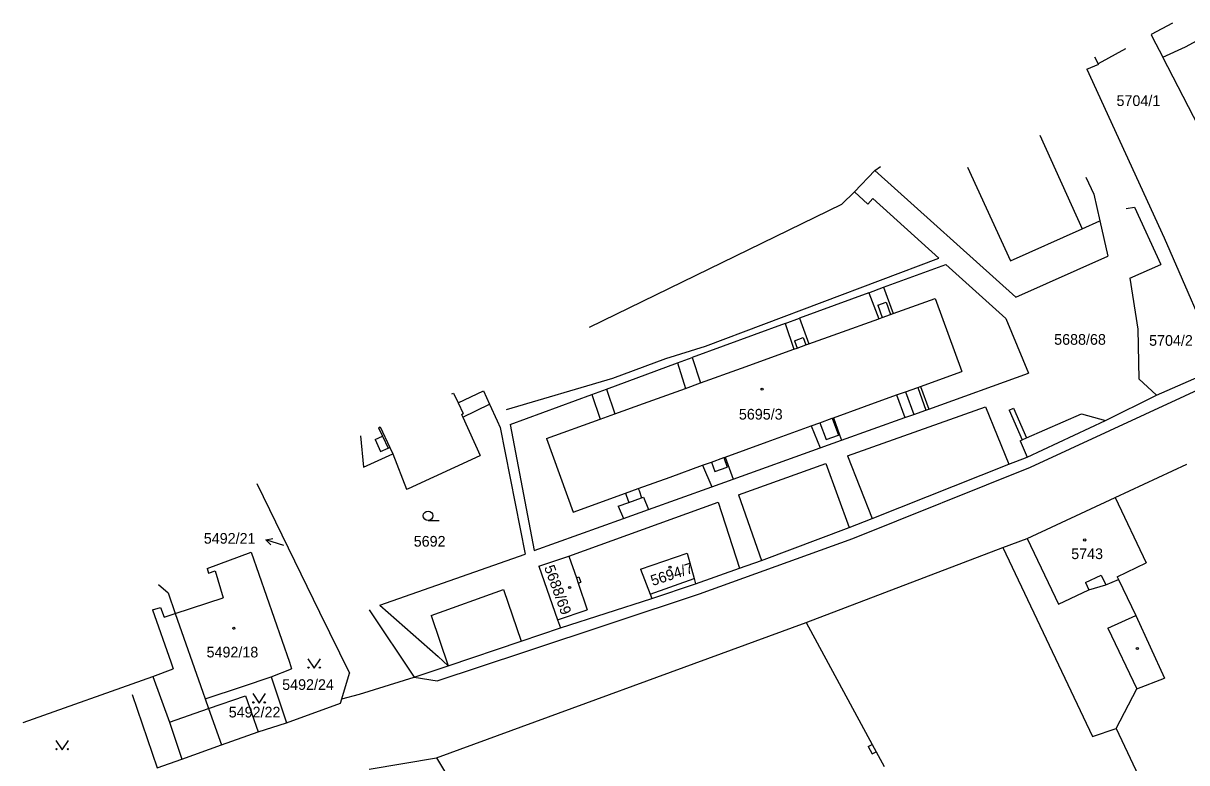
# Model space of a CAD drawing. Extents: x -717507 to -715515, y -957700 to -954941.
# Drawn here: x -716308.1 to -716123.2, y -955290.3 to -955172.6 of the extents above; entities that cross this region are included whole.
import ezdxf

# ---------------------------------------------------------------- set-up
doc = ezdxf.new("R2010")
doc.units = 0
for name, color, linetype in [('Hranice parcel', 7, 'Continuous'), ('Parcelní čísla', 7, 'Continuous'), ('Pop  PČ popisy', 7, 'Continuous'), ('Vnitřní kresba', 7, 'Continuous'), ('Značky budov', 7, 'Continuous'), ('Značky kultur', 7, 'Continuous')]:
    doc.layers.add(name, color=color, linetype=linetype)

msp = doc.modelspace()

# ---------------------------------------------------------------- linework, layer by layer
at = {"layer": 'Hranice parcel'}
for points in [[(-716125.44, -955172.61), (-716128.81, -955174.42)], [(-716126.97, -955178), (-716123.36, -955176.36), (-716118.59, -955173.74)], [(-716128.81, -955174.42), (-716128.64, -955174.77)], [(-716128.64, -955174.77), (-716126.97, -955178)], [(-716137.2, -955179.03), (-716132.84, -955176.61)], [(-716139.07, -955179.92), (-716137.16, -955179.1)], [(-716137.81, -955177.98), (-716137.25, -955179.06)], [(-716137.25, -955179.06), (-716137.2, -955179.03)], [(-716137.16, -955179.1), (-716137.2, -955179.03)], [(-716115.27, -955200.63), (-716115.56, -955200.09), (-716126.97, -955178)], [(-716139.07, -955179.92), (-716126.78, -955206.75)], [(-716175.98, -955199.46), (-716172.74, -955196.06)], [(-716172.74, -955196.06), (-716171.87, -955195.41)], [(-716172.74, -955196.06), (-716150.33, -955216.18)], [(-716158.01, -955195.5), (-716151.21, -955210.39)], [(-716139.23, -955197.08), (-716137.92, -955199.78)], [(-716177.97, -955201.41), (-716175.98, -955199.46)], [(-716175.98, -955199.46), (-716173.88, -955201.39)], [(-716137.92, -955199.78), (-716136.96, -955204.06)], [(-716218.13, -955220.98), (-716177.97, -955201.41)], [(-716173.88, -955201.39), (-716173.08, -955200.5)], [(-716173.08, -955200.5), (-716162.57, -955209.98)], [(-716132.8, -955202.11), (-716131.48, -955201.9)], [(-716131.48, -955201.9), (-716127.26, -955210.98)], [(-716151.21, -955210.39), (-716139.77, -955205.31)], [(-716139.77, -955205.31), (-716136.96, -955204.06)], [(-716136.96, -955204.06), (-716135.69, -955209.66)], [(-716126.78, -955206.75), (-716117.79, -955227.32)], [(-716199.69, -955223.98), (-716162.57, -955209.98)], [(-716171.36, -955214.62), (-716161.46, -955210.98)], [(-716161.46, -955210.98), (-716151.94, -955219.57)], [(-716150.33, -955216.18), (-716135.69, -955209.66)], [(-716132.22, -955213.17), (-716127.26, -955210.98)], [(-716173.71, -955215.48), (-716171.36, -955214.62)], [(-716132.22, -955213.17), (-716130.95, -955221.31)], [(-716173.71, -955215.48), (-716184.73, -955219.54)], [(-716187.03, -955220.38), (-716184.73, -955219.54)], [(-716151.94, -955219.57), (-716148.33, -955228.31)], [(-716187.03, -955220.38), (-716201.77, -955225.8)], [(-716130.95, -955221.31), (-716130.78, -955229.17)], [(-716205.97, -955225.96), (-716199.69, -955223.98)], [(-716204.11, -955226.66), (-716201.77, -955225.8)], [(-716215.4, -955230.81), (-716204.11, -955226.66)], [(-716214.42, -955229.06), (-716205.97, -955225.96)], [(-716127.97, -955231.77), (-716117.79, -955227.32)], [(-716231.28, -955234.08), (-716214.42, -955229.06)], [(-716164.18, -955234), (-716148.33, -955228.31)], [(-716130.78, -955229.17), (-716127.97, -955231.77)], [(-716234.96, -955231.09), (-716234, -955233.23)], [(-716217.72, -955231.66), (-716215.4, -955230.81)], [(-716238.27, -955235.3), (-716234, -955233.23)], [(-716234, -955233.23), (-716232.79, -955235.85)], [(-716230.72, -955236.44), (-716217.72, -955231.66)], [(-716136.09, -955235.84), (-716127.97, -955231.77)], [(-716167.97, -955235.36), (-716166.55, -955234.88)], [(-716166.55, -955234.88), (-716164.62, -955234.17)], [(-716164.62, -955234.17), (-716164.18, -955234)], [(-716238.27, -955235.3), (-716235.47, -955241.41)], [(-716232.79, -955235.85), (-716232.33, -955236.92)], [(-716232.33, -955236.92), (-716228.33, -955257.07)], [(-716230.72, -955236.44), (-716226.89, -955256.5)], [(-716178.05, -955238.97), (-716167.97, -955235.36)], [(-716148.55, -955241.63), (-716136.09, -955235.84)], [(-716254.5, -955238.25), (-716254.03, -955243.26)], [(-716195.28, -955245.16), (-716181.44, -955240.19)], [(-716181.44, -955240.19), (-716178.05, -955238.97)], [(-716254.03, -955243.26), (-716249.39, -955241.11)], [(-716249.39, -955241.11), (-716247.19, -955246.76)], [(-716246.87, -955246.62), (-716235.47, -955241.41)], [(-716151.47, -955242.78), (-716148.55, -955241.63)], [(-716173.18, -955251.42), (-716151.47, -955242.78)], [(-716134.57, -955248.07), (-716123.16, -955242.77)], [(-716270.98, -955245.83), (-716261.02, -955266.33)], [(-716198.68, -955246.37), (-716195.28, -955245.16)], [(-716247.19, -955246.76), (-716246.87, -955246.62)], [(-716208.71, -955249.97), (-716198.68, -955246.37)], [(-716148.53, -955254.6), (-716134.57, -955248.07)], [(-716134.57, -955248.07), (-716129.63, -955258.48)], [(-716226.89, -955256.5), (-716212.71, -955251.41)], [(-716212.71, -955251.41), (-716208.71, -955249.97)], [(-716176.85, -955252.84), (-716173.18, -955251.42)], [(-716190.74, -955258.08), (-716176.85, -955252.84)], [(-716152.41, -955256.05), (-716148.53, -955254.6)], [(-716278.91, -955259.37), (-716271.91, -955256.78)], [(-716271.91, -955256.78), (-716265.81, -955274.25)], [(-716251.46, -955265.22), (-716228.33, -955257.07)], [(-716209.98, -955259.46), (-716202.59, -955256.91)], [(-716202.59, -955256.91), (-716201.46, -955260.96)], [(-716183.68, -955267.96), (-716152.41, -955256.05)], [(-716152.41, -955256.05), (-716138.17, -955286.12)], [(-716226.15, -955259.02), (-716221.4, -955257.38)], [(-716226.15, -955259.02), (-716223.21, -955267.53)], [(-716221.4, -955257.38), (-716220.2, -955260.86)], [(-716194.28, -955259.34), (-716190.74, -955258.08)], [(-716134.23, -955260.69), (-716129.63, -955258.48)], [(-716278.91, -955259.37), (-716278.66, -955260.11)], [(-716278.66, -955260.11), (-716277.64, -955259.74)], [(-716277.64, -955259.74), (-716276.32, -955264.01)], [(-716220.2, -955260.86), (-716219.78, -955260.71)], [(-716219.78, -955260.71), (-716219.49, -955261.55)], [(-716209.98, -955259.46), (-716208.45, -955263.44)], [(-716201.46, -955260.96), (-716201.25, -955261.79)], [(-716201.25, -955261.79), (-716194.28, -955259.34)], [(-716134.23, -955260.69), (-716134.02, -955261.14)], [(-716286.63, -955261.92), (-716285.11, -955263.22)], [(-716219.92, -955261.69), (-716219.49, -955261.55)], [(-716219.92, -955261.69), (-716218.48, -955265.94)], [(-716208.18, -955264.14), (-716201.25, -955261.79)], [(-716134.02, -955261.14), (-716131.26, -955266.83)], [(-716285.11, -955263.22), (-716283.95, -955266.51)], [(-716283.95, -955266.51), (-716276.32, -955264.01)], [(-716222.7, -955268.8), (-716208.18, -955264.14)], [(-716208.45, -955263.44), (-716208.18, -955264.14)], [(-716287.6, -955265.95), (-716284.65, -955274.23)], [(-716283.95, -955266.51), (-716279.55, -955279.05)], [(-716261.02, -955266.33), (-716256.25, -955276.03)], [(-716251.46, -955265.22), (-716242.15, -955273.37)], [(-716223.21, -955267.53), (-716218.48, -955265.94)], [(-716242.42, -955289.49), (-716183.68, -955267.96)], [(-716183.68, -955267.96), (-716173.15, -955287.35)], [(-716131.26, -955266.83), (-716126.69, -955276.83)], [(-716228.97, -955270.91), (-716222.7, -955268.8)], [(-716240.55, -955274.85), (-716228.97, -955270.91)], [(-716242.15, -955273.37), (-716240.55, -955274.85)], [(-716287.5, -955276.56), (-716284.27, -955275.33)], [(-716284.65, -955274.23), (-716284.27, -955275.33)], [(-716268.69, -955276.6), (-716265.5, -955275.32)], [(-716265.81, -955274.25), (-716265.5, -955275.32)], [(-716246, -955276.64), (-716240.55, -955274.85)], [(-716308.12, -955283.88), (-716287.5, -955276.56)], [(-716273.27, -955278.15), (-716268.69, -955276.6)], [(-716268.69, -955276.6), (-716266.3, -955283.9)], [(-716257.46, -955280.08), (-716256.25, -955276.03)], [(-716254.67, -955279.35), (-716246, -955276.64)], [(-716131.12, -955278.54), (-716126.69, -955276.83)], [(-716279.55, -955279.05), (-716279.18, -955280.13)], [(-716279.18, -955280.13), (-716273.27, -955278.15)], [(-716257.46, -955280.08), (-716254.67, -955279.35)], [(-716134.4, -955284.83), (-716131.12, -955278.54)], [(-716279.18, -955280.13), (-716278.65, -955281.64)], [(-716266.3, -955283.9), (-716257.68, -955280.8)], [(-716257.68, -955280.8), (-716257.46, -955280.08)], [(-716278.65, -955281.64), (-716276.62, -955287.45)], [(-716270.78, -955285.38), (-716266.3, -955283.9)], [(-716138.17, -955286.12), (-716134.4, -955284.83)], [(-716134.4, -955284.83), (-716108.55, -955339.69)], [(-716276.62, -955287.45), (-716270.78, -955285.38)], [(-716282.92, -955289.68), (-716276.62, -955287.45)], [(-716173.15, -955287.35), (-716172.52, -955288.52)], [(-716172.52, -955288.52), (-716171.24, -955290.87)], [(-716286.81, -955291.09), (-716282.92, -955289.68)], [(-716253.14, -955291.32), (-716242.42, -955289.49)], [(-716242.42, -955289.49), (-716201.66, -955357.42)]]:
    msp.add_lwpolyline(points, dxfattribs=at)
at = {"layer": 'Pop  PČ popisy'}
for points in [[(-716268.77, -955255.58), (-716269.57, -955254.8), (-716268.47, -955254.62)], [(-716266.71, -955255.7), (-716269.57, -955254.8)]]:
    msp.add_lwpolyline(points, dxfattribs=at)
at = {"layer": 'Vnitřní kresba'}
for points in [[(-716146.53, -955190.42), (-716139.77, -955205.31)], [(-716171.36, -955214.62), (-716169.82, -955218.78)], [(-716173.71, -955215.48), (-716172.14, -955219.62)], [(-716169.82, -955218.78), (-716163.18, -955216.4)], [(-716163.18, -955216.4), (-716158.91, -955228)], [(-716172.28, -955217.49), (-716170.94, -955217.01)], [(-716172.28, -955217.49), (-716171.59, -955219.42)], [(-716170.94, -955217.01), (-716170.25, -955218.94)], [(-716184.73, -955219.54), (-716183.26, -955223.64)], [(-716178.64, -955221.97), (-716172.14, -955219.62)], [(-716172.14, -955219.62), (-716171.59, -955219.42)], [(-716171.59, -955219.42), (-716170.25, -955218.94)], [(-716170.25, -955218.94), (-716169.82, -955218.78)], [(-716187.03, -955220.38), (-716185.6, -955224.48)], [(-716183.26, -955223.64), (-716178.64, -955221.97)], [(-716185.52, -955223.12), (-716184.14, -955222.62)], [(-716185.52, -955223.12), (-716185.09, -955224.3)], [(-716185.09, -955224.3), (-716183.72, -955223.8)], [(-716184.14, -955222.62), (-716183.72, -955223.8)], [(-716183.72, -955223.8), (-716183.26, -955223.64)], [(-716201.77, -955225.8), (-716200.45, -955229.84)], [(-716193.97, -955227.5), (-716185.6, -955224.48)], [(-716185.6, -955224.48), (-716185.09, -955224.3)], [(-716204.11, -955226.66), (-716202.85, -955230.71)], [(-716200.45, -955229.84), (-716193.97, -955227.5)], [(-716165.51, -955230.39), (-716158.91, -955228)], [(-716148, -955243.26), (-716117.16, -955229)], [(-716239, -955233), (-716234.96, -955231.09)], [(-716215.4, -955230.81), (-716214.09, -955234.76)], [(-716209.51, -955233.11), (-716202.85, -955230.71)], [(-716202.85, -955230.71), (-716200.45, -955229.84)], [(-716169.29, -955231.76), (-716167.87, -955231.25)], [(-716167.87, -955231.25), (-716165.94, -955230.55)], [(-716167.87, -955231.25), (-716166.55, -955234.88)], [(-716165.94, -955230.55), (-716165.51, -955230.39)], [(-716165.94, -955230.55), (-716164.62, -955234.17)], [(-716165.51, -955230.39), (-716164.18, -955234)], [(-716239.98, -955231.57), (-716239.71, -955231.45)], [(-716239.71, -955231.45), (-716239, -955233)], [(-716239, -955233), (-716238.21, -955234.72)], [(-716217.72, -955231.66), (-716216.4, -955235.6)], [(-716214.09, -955234.76), (-716209.51, -955233.11)], [(-716174.37, -955233.6), (-716169.29, -955231.76)], [(-716169.29, -955231.76), (-716167.97, -955235.36)], [(-716238.48, -955234.85), (-716238.21, -955234.72)], [(-716238.48, -955234.85), (-716238.27, -955235.3)], [(-716216.4, -955235.6), (-716214.09, -955234.76)], [(-716179.33, -955235.4), (-716174.37, -955233.6)], [(-716177.12, -955241.46), (-716155.14, -955233.64)], [(-716155.14, -955233.64), (-716151.47, -955242.78)], [(-716151.4, -955234.19), (-716150.71, -955233.88)], [(-716151.4, -955234.19), (-716149.32, -955238.89)], [(-716150.71, -955233.88), (-716148.62, -955238.59)], [(-716148.62, -955238.59), (-716139.9, -955234.78)], [(-716139.9, -955234.78), (-716136.09, -955235.84)], [(-716251.63, -955236.96), (-716251.36, -955236.83)], [(-716251.63, -955236.96), (-716251.02, -955238.29)], [(-716251.36, -955236.83), (-716249.86, -955240.09)], [(-716224.97, -955238.68), (-716216.4, -955235.6)], [(-716189.84, -955239.21), (-716182.86, -955236.68)], [(-716182.86, -955236.68), (-716181.47, -955236.18)], [(-716182.86, -955236.68), (-716181.44, -955240.19)], [(-716181.47, -955236.18), (-716179.51, -955235.46)], [(-716181.47, -955236.18), (-716180.5, -955238.86)], [(-716179.51, -955235.46), (-716179.33, -955235.4)], [(-716179.51, -955235.46), (-716178.54, -955238.15)], [(-716179.33, -955235.4), (-716178.37, -955238.09)], [(-716252.2, -955238.83), (-716251.02, -955238.29)], [(-716251.02, -955238.29), (-716250.14, -955240.22)], [(-716224.97, -955238.68), (-716220.69, -955250.38)], [(-716180.5, -955238.86), (-716178.54, -955238.15)], [(-716178.54, -955238.15), (-716178.37, -955238.09)], [(-716178.37, -955238.09), (-716178.05, -955238.97)], [(-716149.32, -955238.89), (-716148.62, -955238.59)], [(-716252.2, -955238.83), (-716251.32, -955240.76)], [(-716251.32, -955240.76), (-716250.14, -955240.22)], [(-716250.14, -955240.22), (-716249.86, -955240.09)], [(-716249.86, -955240.09), (-716249.39, -955241.11)], [(-716196.53, -955241.63), (-716189.84, -955239.21)], [(-716149.65, -955239.04), (-716149.32, -955238.89)], [(-716149.65, -955239.04), (-716148.55, -955241.63)], [(-716200.14, -955242.94), (-716198.73, -955242.43)], [(-716198.73, -955242.43), (-716196.77, -955241.72)], [(-716198.73, -955242.43), (-716198.19, -955243.94)], [(-716196.77, -955241.72), (-716196.53, -955241.63)], [(-716196.77, -955241.72), (-716196.23, -955243.23)], [(-716196.53, -955241.63), (-716195.28, -955245.16)], [(-716177.12, -955241.46), (-716173.18, -955251.42)], [(-716205.31, -955244.81), (-716200.14, -955242.94)], [(-716200.14, -955242.94), (-716198.68, -955246.37)], [(-716198.19, -955243.94), (-716196.23, -955243.23)], [(-716194.43, -955247.63), (-716180.53, -955242.68)], [(-716180.53, -955242.68), (-716176.85, -955252.84)], [(-716176.27, -955254.57), (-716148, -955243.26)], [(-716210.35, -955246.64), (-716205.31, -955244.81)], [(-716220.69, -955250.38), (-716212.38, -955247.37)], [(-716212.38, -955247.37), (-716210.35, -955246.64)], [(-716212.38, -955247.37), (-716212.26, -955247.69)], [(-716212.26, -955247.69), (-716211.85, -955248.84)], [(-716210.35, -955246.64), (-716210.23, -955246.96)], [(-716210.23, -955246.96), (-716209.82, -955248.11)], [(-716209.82, -955248.11), (-716209.53, -955248)], [(-716209.53, -955248), (-716208.71, -955249.97)], [(-716194.43, -955247.63), (-716190.74, -955258.08)], [(-716221.4, -955257.38), (-716197.68, -955248.79)], [(-716213.54, -955249.46), (-716211.85, -955248.84)], [(-716213.54, -955249.46), (-716212.71, -955251.41)], [(-716211.85, -955248.84), (-716209.82, -955248.11)], [(-716197.68, -955248.79), (-716194.28, -955259.34)], [(-716200.6, -955263.39), (-716176.27, -955254.57)], [(-716148.53, -955254.6), (-716143.55, -955265.06)], [(-716220.2, -955260.86), (-716219.92, -955261.69)], [(-716208.45, -955263.44), (-716201.46, -955260.96)], [(-716139.27, -955261.61), (-716136.77, -955260.41)], [(-716136.77, -955260.41), (-716136.01, -955261.99)], [(-716243.28, -955266.84), (-716231.76, -955262.69)], [(-716231.76, -955262.69), (-716228.97, -955270.91)], [(-716143.55, -955265.06), (-716138.73, -955262.74)], [(-716139.27, -955261.61), (-716138.73, -955262.74)], [(-716138.73, -955262.74), (-716136.01, -955261.99)], [(-716136.01, -955261.99), (-716134.02, -955261.14)], [(-716228.41, -955272.64), (-716200.6, -955263.39)], [(-716287.6, -955265.95), (-716286.28, -955265.57)], [(-716286.28, -955265.57), (-716285.72, -955267.1)], [(-716285.72, -955267.1), (-716283.95, -955266.51)], [(-716253.15, -955265.92), (-716246, -955276.64)], [(-716243.28, -955266.84), (-716240.55, -955274.85)], [(-716223.21, -955267.53), (-716222.7, -955268.8)], [(-716135.69, -955268.84), (-716131.26, -955266.83)], [(-716135.69, -955268.84), (-716131.12, -955278.54)], [(-716242.3, -955277.24), (-716228.41, -955272.64)], [(-716287.5, -955276.56), (-716284.89, -955283.8)], [(-716246, -955276.64), (-716242.3, -955277.24)], [(-716290.79, -955279.43), (-716286.81, -955291.09)], [(-716278.65, -955281.64), (-716272.78, -955279.61)], [(-716272.78, -955279.61), (-716270.78, -955285.38)], [(-716284.89, -955283.8), (-716278.65, -955281.64)], [(-716284.89, -955283.8), (-716282.92, -955289.68)], [(-716173.81, -955287.7), (-716173.15, -955287.35)], [(-716173.81, -955287.7), (-716173.18, -955288.88)], [(-716173.18, -955288.88), (-716172.52, -955288.52)]]:
    msp.add_lwpolyline(points, dxfattribs=at)
at = {"layer": 'Značky budov'}
for centre in [(-716190.67, -955230.84), (-716139.38, -955254.83), (-716205.32, -955259.16), (-716221.27, -955262.39), (-716274.65, -955268.87), (-716131.02, -955272.09)]:
    msp.add_circle(centre, 0.175, dxfattribs=at)
at = {"layer": 'Značky kultur'}
for points in [[(-716243.78, -955251.73), (-716242.03, -955251.73)], [(-716262.88, -955273.74), (-716261.88, -955275.24), (-716260.88, -955273.74)], [(-716271.63, -955279.27), (-716270.63, -955280.77), (-716269.63, -955279.27)], [(-716302.93, -955286.71), (-716301.93, -955288.21), (-716300.93, -955286.71)]]:
    msp.add_lwpolyline(points, dxfattribs=at)
for centre, radius in [((-716243.78, -955250.98), 0.75), ((-716262.78, -955275.14), 0.1), ((-716260.98, -955275.14), 0.1), ((-716271.53, -955280.67), 0.1), ((-716269.73, -955280.67), 0.1), ((-716302.83, -955288.11), 0.1), ((-716301.03, -955288.11), 0.1)]:
    msp.add_circle(centre, radius, dxfattribs=at)

# ---------------------------------------------------------------- texts
at = {"layer": 'Parcelní čísla'}
for s, p in [('5704/1', (-716134.33, -955185.78)), ('5688/68', (-716144.24, -955223.77)), ('5704/2', (-716129.15, -955223.93)), ('5695/3', (-716194.36, -955235.67)), ('5492/21', (-716279.42, -955255.42)), ('5692', (-716246.05, -955255.89)), ('5743', (-716141.53, -955257.87)), ('5492/18', (-716278.98, -955273.52)), ('5492/24', (-716266.96, -955278.69)), ('5492/22', (-716275.46, -955283.07))]:
    msp.add_text(s, height=1.7, dxfattribs=at).set_placement(p)
for s, rotation, p in [('5688/69', 290.1023, (-716225.35, -955259.18)), ('5694/7', 18.1001, (-716208.06, -955262.16))]:
    msp.add_text(s, height=1.7, rotation=rotation, dxfattribs=at).set_placement(p)

doc.saveas('drawing.dxf')
